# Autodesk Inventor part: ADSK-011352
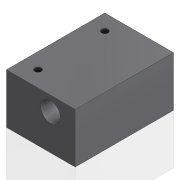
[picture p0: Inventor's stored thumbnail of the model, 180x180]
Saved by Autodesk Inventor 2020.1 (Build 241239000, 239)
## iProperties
Created: 1999-12
Part Number: ADSK-011352
Material: Acier doux
Document SubType Name: Modeling
Designer: sspink
Density: 7.86 g/cm^3
Appearance: Metal-Steel(Polish)
Mass: 314.757 g
Surface Area: 96.1456 cm^2
Volume: 40.0454 cm^3
Control State: 0
Checked Out: False
Master: False
Shininess: 0.0
Length Units: 11269
Angle Units: 11279
Time Units: 11290
Mass Units: 11283
Length Display Precision: 3
Angle Display Precision: 2
Compacted: True
Cutlength: 1.38
Material Desc: FLAT,HRS, 1.00 X 2.00
Material_number: A084363
Dimensions: 34,9x25,4x50 mm
Mass: 0,315 kg
DocNumber: ADSK-011352.ipt
Folder: 01 - Themengebiete\Simplification\01 - Packaging machine\
VDS_Category: 3D Komponenten
Density: 0.0
Volumn: 0.0
Area: 0.0
PropertySet Name: Model Information
Author: sspink
Revision Number: -
Title: bracket
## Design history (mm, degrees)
node "Solide1"
  node "Extrusion1" dims "d2" = 50, "d3" = 0
  node "Hole1" dims "d4" = 10, "d5" = 9.525, "d6" = 6.35, "d7" = 60 deg, "d8" = 19.05, "d9" = 118 deg, "d33" = 6
  node "Hole2" dims "d10" = 4.134, "d11" = 9.525, "d12" = 6.35, "d13" = 60 deg, "d14" = 14.2, "d15" = 118 deg, "d34" = 10
  node "Hole3" dims "d25" = 3.242, "d26" = 9.525, "d27" = 6.35, "d28" = 60 deg, "d29" = 11.8, "d30" = 118 deg, "d36" = 8
sketch "Sketch1"
  geometry: L1 (17.462, 12.7)-(-17.462, 12.7); L2 (-17.462, 12.7)-(-17.462, -12.7); L3 (-17.462, -12.7)-(17.462, -12.7); L4 (17.462, -12.7)-(17.462, 12.7); 3 further points
  constraints: 8 end point, 2 midpoint, 2 parallel, 1 horizontal, 1 horizontal alignment, 1 perpendicular, 1 vertical alignment
  dimensions: "d0" = 34.925 distance of L2.end L3.end; "d1" = 25.4 distance of L3.end L1.start
sketch "Sketch2"
  geometry: L1 (-17.462, 12.7)-(17.462, 12.7) reference; L2 (-17.462, -12.7)-(-17.462, 12.7) reference; L3 (17.462, -12.7)-(-17.462, -12.7) reference; L4 (0, -12.7)-(0, 12.7); 1 further point
  constraints: 2 end point, 2 midpoint
  dimensions: "d19" = 18 distance from line of point (-4.962, 5.3) L3; "d20" = 12.5 distance from line of point (-4.962, 5.3) L2
workaxis "Arbeitsachse1"
workplane "Arbeitsebene1"
sketch "Sketch3"
  geometry: L1 (0, 0)-(0, 50) reference; 3 further points
  constraints: 1 horizontal alignment, 1 midpoint
  dimensions: "d31" = 22 distance from line of point (22, 25) L1
sketch "Sketch4"
  geometry: L1 (0, 0)-(0, -50) reference; L2 (8, -42)-(8, -8); 2 further points
  constraints: 2 end point, 2 midpoint, 1 horizontal alignment, 1 vertical
  dimensions: "d22" = 8 distance from line of L1 L2.start; "d35" = 34 distance of L2.start L2.end
node "Corps solides"
node "Corps surfaciques"
other parameters: "d37" = 90 deg
